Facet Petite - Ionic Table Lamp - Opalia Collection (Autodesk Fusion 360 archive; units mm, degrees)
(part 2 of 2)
create_component "CreateComponent4"
create_component "CreateComponent5"
create_component "CreateComponent6"
create_component "CreateComponent7"
create_component "CreateComponent8"
remove_body "RemoveBody1"
create_component "CreateComponent9"
create_component "CreateComponent10"
create_component "CreateComponent11"
create_component "CreateComponent12"
create_component "CreateComponent13"
create_component "CreateComponent14"
create_component "CreateComponent15"
create_component "CreateComponent16"
create_component "CreateComponent17"
create_component "CreateComponent18"
remove_body "RemoveBody6"
create_component "CreateComponent19"
create_component "CreateComponent20"
create_component "CreateComponent21"
create_component "CreateComponent22"
create_component "CreateComponent23"
named bodies: "Marble Base", "Rotary Switch", "Coiled - SVT (Blk Fabric)", "Glass Globe", "Metal Housing", "Metal Socket Cover", "Porcelain Socket", "Brass Dial - Dimmer Knob", "Solitaire Petite", "Facet Petite", "Body1", "Body2", "Plastic Insert", "Silicone Gasket", "Oculo Petite", "Balon v2", "Balon v3", "Trove - TL", "Trove - TL (1)", "Neoprene Pad", "2-Pole Plug End", "Rubber Grommet", "Chinois"

design "Trove - TL"
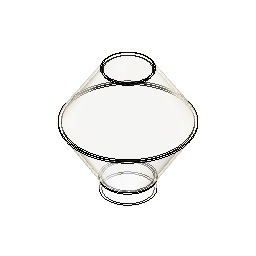
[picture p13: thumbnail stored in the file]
derived_base_feature "Derived Base Feature" bodies "Trove"
hole "Hole1" HoleDepth 88.9 HoleDiameter 44.45 TipAngle 118
sketch "Sketch1" plane through (0, 0, 0) normal (1, 0, 0) x axis (0, 1, 0)
  line L1 (0, 243.0601) -> (0, 247.8226)
  line L2 (-50.8, -12.7122) -> (-50.8, 10.9447)
  line L3 (0, -25.4) -> (0, 243.0601)
  line L4 (-46.0375, -12.7122) -> (-50.8, -12.7122)
  line L5 (-46.0375, -12.7122) -> (-46.0375, 12.3043)
  line L6 (-45.9716, 247.8226) -> (0, 247.8226)
  line L7 (-43.3841, 243.0601) -> (0, 243.0601)
  line L8 (-122.8321, 128.6352) -> (-51.757, 14.2971)
  line L9 (-117.1907, 128.5808) -> (-46.9945, 15.6567)
  line L10 (-48.6353, 246.3754) -> (-122.7993, 132.0392)
  line L11 (-46.0478, 241.6129) -> (-117.1579, 131.9848)
  arc A1 centre (-57.15, 10.9447) radius 6.35 clockwise from (-51.757, 14.2971) to (-50.8, 10.9447)
  arc A2 centre (-52.3875, 12.3043) radius 6.35 clockwise from (-46.9945, 15.6567) to (-46.0375, 12.3043)
  arc A3 centre (-114.4942, 130.257) radius 3.175 between (-117.1579, 131.9848) and (-117.1907, 128.5808)
  arc A4 centre (-120.1356, 130.3114) radius 3.175 between (-122.7993, 132.0392) and (-122.8321, 128.6352)
  arc A5 centre (-45.9716, 244.6476) radius 3.175 between (-45.9716, 247.8226) and (-48.6353, 246.3754)
  arc A6 centre (-43.3841, 239.8851) radius 3.175 clockwise from (-46.0478, 241.6129) to (-43.3841, 243.0601)
  point P3 (0, 247.8226)
  point P4 (0, 243.0601)
  vertical L1
  vertical L3
  tangent L5 A2
  perpendicular L1 L6
  perpendicular L1 L7
  tangent L11 A3
  tangent L9 A3
  tangent L10 A4
  tangent L8 A4
  equal A3 A4
  tangent L6 A5
  tangent L10 A5
  tangent L11 A6
  tangent L7 A6
  dimension "d8" distance P3 P4 = 4.7625
  dimension "d11" radius A2 = 6.35
  dimension "d15" radius A3 = 3.175
  dimension "d16" radius A5 = 3.175
  dimension "d17" radius A6 = 3.175
revolve "Revolve1" sketch "Sketch1" AlongAngle 180 bodies "Trove - TL"
revolve "Revolve2" sketch "Sketch1" AlongAngle -180
component_from_bodies "Body->Comp"
remove_body "RemoveBody2"
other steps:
base_feature "Base Feature" bodies "Trove - TL"
create_component "CreateComponent1"
remove_body "RemoveBody1"
named bodies: "Trove", "Trove - TL"

design "T9-5In"
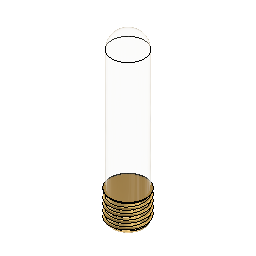
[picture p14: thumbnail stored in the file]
sketch "Sketch1" plane through (0, 0, 0) normal (0, 1, 0) x axis (1, 0, 0)
  line L1 (0, 0) -> (0, -127)
  line L2 (12.7, -127) -> (-12.7, -127)
  line L3 (12.7, -12.7) -> (12.7, -127)
  line L4 (-12.7, -127) -> (-12.7, -12.7)
  arc A1 centre (0, -12.7) radius 12.7 clockwise from (-12.7, -12.7) to (12.7, -12.7)
  point P1 (0, 0)
  point P3 (0, 0)
  coincident P1 P3
  vertical L1
  horizontal L2
  vertical L3
  vertical L4
revolve "Revolve1" sketch "Sketch1" AlongAngle 360 bodies "BU-T10-5-LED-120V"
derived_base_feature "Derived Base Feature" bodies "E26 Base"
move "Move1"
component_from_bodies "Body->Comp"
copy_paste "CutPaste"
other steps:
base_feature "Base Feature" bodies "BU-T10-5-LED-120V"
create_component "CreateComponent1"
create_component "CreateComponent2"
remove_body "RemoveBody1"
remove_instance "RemoveInstance1"
named bodies: "BU-T10-5-LED-120V", "E26 Base"

design "Balon v2"
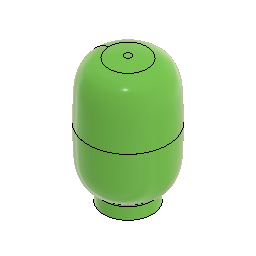
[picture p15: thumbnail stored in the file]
derived_base_feature "Derived Base Feature" bodies "Balon"
work_plane "WorkPlane1" AlongDistance 0
sketch "Sketch1" plane through (0, 0, 0) normal (0, 1, 0) x axis (1, 0, 0)
  line L1 (0, 317.5) -> (0, 2.9083)
  curve K1 (-82.9821, 124.2212) -> (-50.8, 237.8015)
  curve K2 (-51.0925, 237.681) -> (-50.8, 237.8015)
  curve K3 (-51.3855, 237.5558) -> (-51.0925, 237.681)
  curve K4 (-54.7608, 236.0513) -> (-51.3855, 237.5558)
  curve K5 (-57.9615, 234.05) -> (-54.7608, 236.0513)
  curve K6 (-67.2727, 226.749) -> (-57.9615, 234.05)
  curve K7 (-69.0552, 224.2615) -> (-67.2727, 226.749)
  curve K8 (-72.1872, 218.7832) -> (-69.0552, 224.2615)
  curve K9 (-74.1213, 215.1556) -> (-72.1872, 218.7832)
  curve K10 (-78.3031, 204.3965) -> (-74.1213, 215.1556)
  curve K11 (-79.7275, 197.3397) -> (-78.3031, 204.3965)
  curve K12 (-81.3333, 185.4664) -> (-79.7275, 197.3397)
  curve K13 (-81.6254, 178.4008) -> (-81.3333, 185.4664)
  curve K14 (-82.49, 152.2133) -> (-81.6254, 178.4008)
  curve K15 (-82.9821, 136.067) -> (-82.49, 152.2133)
  curve K16 (-82.9821, 124.2212) -> (-82.9821, 136.067)
  curve K17 (50.8, 237.7999) -> (82.9821, 124.2212)
  curve K18 (82.9821, 140.3031) -> (82.9821, 124.2212)
  curve K19 (81.9353, 169.4257) -> (82.9821, 140.3031)
  curve K20 (81.3621, 183.6489) -> (81.9353, 169.4257)
  curve K21 (80.9478, 189.8724) -> (81.3621, 183.6489)
  curve K22 (77.8147, 206.9858) -> (80.9478, 189.8724)
  curve K23 (74.9652, 213.2153) -> (77.8147, 206.9858)
  curve K24 (69.4688, 224.1531) -> (74.9652, 213.2153)
  curve K25 (67.2512, 226.458) -> (69.4688, 224.1531)
  curve K26 (61.5696, 231.3138) -> (67.2512, 226.458)
  curve K27 (57.377, 234.6711) -> (61.5696, 231.3138)
  curve K28 (52.0556, 237.2628) -> (57.377, 234.6711)
  curve K29 (51.4313, 237.5413) -> (52.0556, 237.2628)
  curve K30 (50.8, 237.7999) -> (51.4313, 237.5413)
  line L2 (-50.8, 317.5) -> (-50.8, 237.8015)
  line L3 (50.8, 317.5) -> (50.8, 237.7999)
  line L4 (-19.0713, 6.7501) -> (-19.0713, 6.7501)
  curve K31 (82.9821, 124.1958) -> (40.1509, 7.3012)
  curve K32 (41.8198, 7.6176) -> (40.1509, 7.3012)
  curve K33 (43.2113, 8.0663) -> (41.8198, 7.6176)
  curve K34 (47.0139, 9.2854) -> (43.2113, 8.0663)
  curve K35 (47.3314, 9.3805) -> (47.0139, 9.2854)
  curve K36 (50.1192, 10.3272) -> (47.3314, 9.3805)
  curve K37 (51.833, 11.0085) -> (50.1192, 10.3272)
  curve K38 (57.8313, 14.1895) -> (51.833, 11.0085)
  curve K39 (61.4491, 17.0488) -> (57.8313, 14.1895)
  curve K40 (66.8203, 21.5867) -> (61.4491, 17.0488)
  curve K41 (68.5372, 23.5528) -> (66.8203, 21.5867)
  curve K42 (71.2201, 27.8971) -> (68.5372, 23.5528)
  curve K43 (74.7424, 33.8984) -> (71.2201, 27.8971)
  curve K44 (78.2342, 44.8406) -> (74.7424, 33.8984)
  curve K45 (79.6792, 50.3463) -> (78.2342, 44.8406)
  curve K46 (81.3558, 63.5576) -> (79.6792, 50.3463)
  curve K47 (81.6386, 70.4415) -> (81.3558, 63.5576)
  curve K48 (82.4897, 96.2198) -> (81.6386, 70.4415)
  curve K49 (82.9814, 112.3523) -> (82.4897, 96.2198)
  curve K50 (82.9821, 124.1958) -> (82.9814, 112.3523)
  curve K51 (-40.1501, 7.301) -> (-82.9821, 124.1958)
  curve K52 (-82.9813, 110.5256) -> (-82.9821, 124.1958)
  curve K53 (-82.2545, 88.8594) -> (-82.9813, 110.5256)
  curve K54 (-81.6277, 70.519) -> (-82.2545, 88.8594)
  curve K55 (-81.3572, 64.3441) -> (-81.6277, 70.519)
  curve K56 (-79.4149, 46.8924) -> (-81.3572, 64.3441)
  curve K57 (-76.5204, 38.9768) -> (-79.4149, 46.8924)
  curve K58 (-73.5142, 32.2947) -> (-76.5204, 38.9768)
  curve K59 (-72.5556, 30.3818) -> (-73.5142, 32.2947)
  curve K60 (-69.7914, 25.3691) -> (-72.5556, 30.3818)
  curve K61 (-68.3824, 23.4028) -> (-69.7914, 25.3691)
  curve K62 (-64.5419, 19.5456) -> (-68.3824, 23.4028)
  curve K63 (-62.3002, 17.7646) -> (-64.5419, 19.5456)
  curve K64 (-53.6583, 11.1976) -> (-62.3002, 17.7646)
  curve K65 (-49.6968, 10.1396) -> (-53.6583, 11.1976)
  curve K66 (-43.4141, 8.1331) -> (-49.6968, 10.1396)
  curve K67 (-41.9704, 7.6516) -> (-43.4141, 8.1331)
  curve K68 (-40.1963, 7.3098) -> (-41.9704, 7.6516)
  curve K69 (-40.1732, 7.3054) -> (-40.1963, 7.3098)
  curve K70 (-40.1501, 7.301) -> (-40.1732, 7.3054)
  line L5 (-82.9821, 124.1958) -> (-82.9821, 124.2212)
  line L6 (82.9821, 124.2212) -> (82.9821, 124.1958)
  line L7 (0, 317.5) -> (-50.8, 317.5)
  line L8 (7.2015, 3.048) -> (0, 3.048)
  line L9 (0, 3.048) -> (-7.2015, 3.048)
  arc A1 centre (0, 188.595) radius 185.6867 clockwise from (-7.2015, 3.048) to (-40.1502, 7.301)
  arc A2 centre (0, 188.595) radius 185.6867 clockwise from (40.151, 7.3012) to (7.2015, 3.048)
  point P38 (-40.1502, 7.301)
  point P43 (40.1509, 7.3012)
  point P62 (-40.1501, 7.301)
  point P81 (40.151, 7.3012)
  point P84 (0, 3.048)
  vertical L1
  horizontal L4
  coincident P38 K51
  symmetric L1 A1 A2
  coincident A2 P43
  coincident A1 P62
  coincident K31 P81
  perpendicular L2 L7
  horizontal L8
  coincident L1 P84
  horizontal L9
revolve "Revolve1" sketch "Sketch1" AlongAngle 360
shell "Shell1" innerThickness 3.81
fillet "Fillet1" radius 6.35
offset_faces "OffsetFaces1" distance -50.8
move "Move1"
move "Move2"
component_from_bodies "Body->Comp1"
component_from_bodies "Body->Comp2"
sketch "Sketch2" plane through (0, 0, 0) normal (0, 1, 0) x axis (1, 0, 0)
  line L1 (-85.5221, 124.2212) -> (-85.5221, 124.1961)
  curve K1 (-58.9057, 236.4383) -> (-50.8, 241.7989)
  curve K2 (-50.8, 241.554) -> (-50.8, 241.7989)
  curve K3 (-50.904, 240.933) -> (-50.8, 241.554)
  curve K4 (-51.2936, 240.2837) -> (-50.904, 240.933)
  curve K5 (-51.734, 239.7561) -> (-51.2936, 240.2837)
  curve K6 (-53.328, 238.5038) -> (-51.734, 239.7561)
  curve K7 (-54.0892, 238.1997) -> (-53.328, 238.5038)
  curve K8 (-58.9057, 236.4383) -> (-54.0892, 238.1997)
  curve K9 (-89.3309, 124.2212) -> (-58.9057, 236.4383)
  curve K10 (-62.6336, 234.9735) -> (-58.9057, 236.4383)
  curve K11 (-65.581, 233.1032) -> (-62.6336, 234.9735)
  curve K12 (-73.0224, 227.0019) -> (-65.581, 233.1032)
  curve K13 (-74.8981, 224.836) -> (-73.0224, 227.0019)
  curve K14 (-78.1104, 219.6097) -> (-74.8981, 224.836)
  curve K15 (-80.2663, 215.561) -> (-78.1104, 219.6097)
  curve K16 (-84.0943, 205.8277) -> (-80.2663, 215.561)
  curve K17 (-85.4655, 200.1154) -> (-84.0943, 205.8277)
  curve K18 (-87.4092, 188.5789) -> (-85.4655, 200.1154)
  curve K19 (-87.7349, 182.3889) -> (-87.4092, 188.5789)
  curve K20 (-88.4233, 165.9645) -> (-87.7349, 182.3889)
  curve K21 (-89.328, 138.6964) -> (-88.4233, 165.9645)
  curve K22 (-89.3309, 124.2212) -> (-89.328, 138.6964)
  line L2 (-89.3309, 124.1958) -> (-89.3309, 124.2212)
  curve K23 (-46.5001, 7.301) -> (-89.3309, 124.1958)
  curve K24 (-89.3314, 112.4293) -> (-89.3309, 124.1958)
  curve K25 (-88.8181, 95.3068) -> (-89.3314, 112.4293)
  curve K26 (-88.346, 81.2892) -> (-88.8181, 95.3068)
  curve K27 (-88.0298, 70.4902) -> (-88.346, 81.2892)
  curve K28 (-87.1514, 58.328) -> (-88.0298, 70.4902)
  curve K29 (-86.3326, 50.6119) -> (-87.1514, 58.328)
  curve K30 (-81.0932, 33.6688) -> (-86.3326, 50.6119)
  curve K31 (-77.3163, 27.4309) -> (-81.0932, 33.6688)
  curve K32 (-74.8955, 23.6666) -> (-77.3163, 27.4309)
  curve K33 (-73.5108, 22.0741) -> (-74.8955, 23.6666)
  curve K34 (-70.2346, 19.0457) -> (-73.5108, 22.0741)
  curve K35 (-64.8094, 14.3548) -> (-70.2346, 19.0457)
  curve K36 (-56.6696, 10.3041) -> (-64.8094, 14.3548)
  curve K37 (-54.0053, 9.483) -> (-56.6696, 10.3041)
  curve K38 (-49.1487, 7.9411) -> (-54.0053, 9.483)
  curve K39 (-48.3482, 7.6526) -> (-49.1487, 7.9411)
  curve K40 (-46.5001, 7.301) -> (-48.3482, 7.6526)
  line L3 (0, 266.7) -> (0, 0)
  line L4 (0, 3.048) -> (-7.7894, 3.048)
  line L5 (-50.8, 266.7) -> (-50.8, 241.7989)
  line L6 (0, 266.7) -> (-50.8, 266.7)
  arc A1 centre (-6.9779, 188.7329) radius 185.6867 clockwise from (-7.7894, 3.048) to (-46.5001, 7.301)
  point P1 (0, 0)
  point P44 (0, 0)
  point P46 (0, 3.048)
  point P5 (-50.8, 241.554)
  point P49 (0, 266.7)
  coincident P1 P44
  coincident L3 P46
  coincident P5 L5
  coincident L3 P49
revolve "Revolve2" sketch "Sketch2" AlongAngle 360 bodies "Balon v3"
shell "Shell2" innerThickness 3.81
component_from_bodies "Body->Comp3"
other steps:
base_feature "Base Feature1" bodies "Balon"
base_feature "Base Feature1" bodies "Balon v3"
base_feature "Base Feature1" bodies "Balon v2"
create_component "CreateComponent1"
remove_body "RemoveBody1"
create_component "CreateComponent2"
remove_body "RemoveBody2"
create_component "CreateComponent3"
remove_body "RemoveBody3"
named bodies: "Balon", "Balon v2", "Balon v3"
